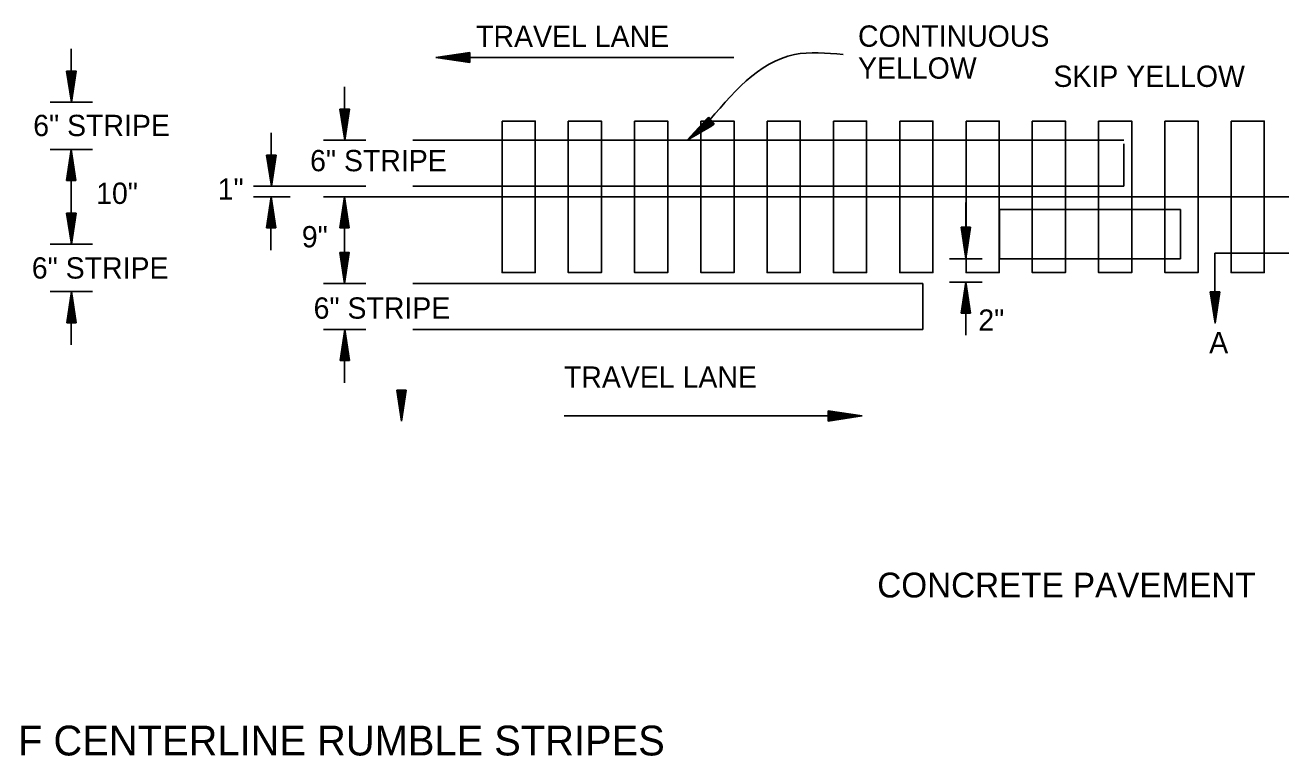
# Model space of a CAD drawing. Extents: x 28704 to 32542, y 50360 to 59122.
# Drawn here: x 31666 to 32184, y 50963 to 51264 of the extents above; entities that cross this region are included whole.
import ezdxf

# ---------------------------------------------------------------- set-up
doc = ezdxf.new("R2010")
doc.units = 0
doc.layers.add('Default', color=7, linetype='Continuous')
doc.layers.add('R_Alt Surface', color=7, linetype='Continuous')

msp = doc.modelspace()

# ---------------------------------------------------------------- linework, layer by layer
at = {"layer": 'Default'}
for p, q in [((31685.25, 51253.97), (31685.25, 51244.83)), ((31849.43, 51252.56), (31835.46, 51250.47)), ((31849.43, 51252.21), (31837.79, 51250.47)), ((31849.43, 51251.86), (31840.19, 51250.47)), ((31849.43, 51251.51), (31842.52, 51250.47)), ((31849.43, 51252.56), (31849.43, 51248.37)), ((31958.25, 51250.47), (31835.46, 51250.47)), ((31849.43, 51248.37), (31835.46, 51250.47)), ((31849.43, 51248.72), (31837.79, 51250.47)), ((31849.43, 51249.08), (31840.19, 51250.47)), ((31849.43, 51249.43), (31842.52, 51250.47)), ((31849.43, 51251.14), (31844.89, 51250.47)), ((31849.43, 51249.78), (31844.89, 51250.47)), ((31849.43, 51250.79), (31847.22, 51250.47)), ((31849.43, 51250.14), (31847.22, 51250.47)), ((31683.39, 51244.83), (31685.31, 51232.03)), ((31683.39, 51244.83), (31687.23, 51244.83)), ((31683.71, 51244.83), (31685.31, 51234.17)), ((31684.03, 51244.83), (31685.31, 51236.37)), ((31684.35, 51244.83), (31685.31, 51238.5)), ((31684.69, 51244.83), (31685.31, 51240.67)), ((31685.01, 51244.83), (31685.31, 51242.81)), ((31687.23, 51244.83), (31685.31, 51232.03)), ((31685.94, 51244.83), (31685.31, 51240.67)), ((31686.58, 51244.83), (31685.31, 51236.37)), ((31686.91, 51244.83), (31685.31, 51234.17)), ((31686.26, 51244.83), (31685.31, 51238.5)), ((31685.61, 51244.83), (31685.31, 51242.81)), ((31797.86, 51238.33), (31797.86, 51229.19)), ((31676.56, 51232.03), (31694.06, 51232.03)), ((31796, 51229.19), (31797.92, 51216.39)), ((31796, 51229.19), (31799.84, 51229.19)), ((31796.32, 51229.19), (31797.92, 51218.53)), ((31796.65, 51229.19), (31797.92, 51220.73)), ((31796.97, 51229.19), (31797.92, 51222.86)), ((31797.3, 51229.19), (31797.92, 51225.03)), ((31797.62, 51229.19), (31797.92, 51227.17)), ((31799.84, 51229.19), (31797.92, 51216.39)), ((31798.55, 51229.19), (31797.92, 51225.03)), ((31799.19, 51229.19), (31797.92, 51220.73)), ((31799.52, 51229.19), (31797.92, 51218.53)), ((31798.87, 51229.19), (31797.92, 51222.86)), ((31798.22, 51229.19), (31797.92, 51227.17)), ((31947.74, 51225.9), (31938.96, 51216.39)), ((31947.94, 51225.66), (31940.62, 51217.73)), ((31948.14, 51225.4), (31942.34, 51219.11)), ((31947.74, 51225.9), (31950.14, 51222.91)), ((31950.14, 51222.91), (31938.96, 51216.39)), ((31949.94, 51223.16), (31940.62, 51217.73)), ((31949.74, 51223.41), (31942.34, 51219.11)), ((31948.34, 51225.15), (31944, 51220.44)), ((31949.54, 51223.66), (31944, 51220.44)), ((31948.55, 51224.89), (31945.69, 51221.8)), ((31949.33, 51223.92), (31945.69, 51221.8)), ((31948.75, 51224.64), (31947.36, 51223.14)), ((31949.13, 51224.17), (31947.36, 51223.14)), ((31767.65, 51219.34), (31767.65, 51210.2)), ((31789.17, 51216.39), (31806.67, 51216.39)), ((31676.56, 51212.52), (31694.06, 51212.52)), ((31683.33, 51199.72), (31685.25, 51212.52)), ((31683.65, 51199.72), (31685.25, 51210.38)), ((31685.25, 51173.51), (31685.25, 51212.52)), ((31687.17, 51199.72), (31685.25, 51212.52)), ((31686.85, 51199.72), (31685.25, 51210.38)), ((31765.79, 51210.2), (31767.71, 51197.4)), ((31765.79, 51210.2), (31769.63, 51210.2)), ((31766.11, 51210.2), (31767.71, 51199.53)), ((31766.43, 51210.2), (31767.71, 51201.74)), ((31766.76, 51210.2), (31767.71, 51203.87)), ((31767.09, 51210.2), (31767.71, 51206.04)), ((31767.41, 51210.2), (31767.71, 51208.18)), ((31769.63, 51210.2), (31767.71, 51197.4)), ((31768.34, 51210.2), (31767.71, 51206.04)), ((31768.98, 51210.2), (31767.71, 51201.74)), ((31769.31, 51210.2), (31767.71, 51199.53)), ((31768.66, 51210.2), (31767.71, 51203.87)), ((31768.01, 51210.2), (31767.71, 51208.18)), ((31683.98, 51199.72), (31685.25, 51208.18)), ((31684.3, 51199.72), (31685.25, 51206.05)), ((31686.52, 51199.72), (31685.25, 51208.18)), ((31686.2, 51199.72), (31685.25, 51206.05)), ((31687.17, 51199.72), (31683.33, 51199.72)), ((31684.62, 51199.72), (31685.25, 51203.88)), ((31684.95, 51199.72), (31685.25, 51201.74)), ((31685.87, 51199.72), (31685.25, 51203.88)), ((31685.55, 51199.72), (31685.25, 51201.74)), ((31760.33, 51197.4), (31806.67, 51197.4)), ((31760.33, 51193.02), (31775.49, 51193.02)), ((31765.62, 51180.21), (31767.54, 51193.02)), ((31765.94, 51180.21), (31767.54, 51190.88)), ((31769.46, 51180.21), (31767.54, 51193.02)), ((31769.15, 51180.21), (31767.54, 51190.88)), ((31789.17, 51193.02), (32417.27, 51193.02)), ((31795.94, 51180.21), (31797.86, 51193.02)), ((31796.26, 51180.21), (31797.86, 51190.88)), ((31797.86, 51157.37), (31797.86, 51193.02)), ((31799.78, 51180.21), (31797.86, 51193.02)), ((31799.46, 51180.21), (31797.86, 51190.88)), ((32053.75, 51167.71), (32053.75, 51190.77)), ((31683.39, 51186.31), (31685.31, 51173.51)), ((31683.39, 51186.31), (31687.23, 51186.31)), ((31683.71, 51186.31), (31685.31, 51175.65)), ((31684.03, 51186.31), (31685.31, 51177.85)), ((31684.35, 51186.31), (31685.31, 51179.98)), ((31684.69, 51186.31), (31685.31, 51182.15)), ((31685.01, 51186.31), (31685.31, 51184.29)), ((31687.23, 51186.31), (31685.31, 51173.51)), ((31685.94, 51186.31), (31685.31, 51182.15)), ((31686.58, 51186.31), (31685.31, 51177.85)), ((31686.91, 51186.31), (31685.31, 51175.65)), ((31686.26, 51186.31), (31685.31, 51179.98)), ((31685.61, 51186.31), (31685.31, 51184.29)), ((31766.27, 51180.21), (31767.54, 51188.68)), ((31766.59, 51180.21), (31767.54, 51186.54)), ((31766.92, 51180.21), (31767.54, 51184.37)), ((31768.82, 51180.21), (31767.54, 51188.68)), ((31768.5, 51180.21), (31767.54, 51186.54)), ((31768.17, 51180.21), (31767.54, 51184.37)), ((31796.59, 51180.21), (31797.86, 51188.68)), ((31796.91, 51180.21), (31797.86, 51186.54)), ((31797.24, 51180.21), (31797.86, 51184.37)), ((31799.14, 51180.21), (31797.86, 51188.68)), ((31798.82, 51180.21), (31797.86, 51186.54)), ((31798.49, 51180.21), (31797.86, 51184.37)), ((31769.46, 51180.21), (31765.62, 51180.21)), ((31767.25, 51180.21), (31767.55, 51182.23)), ((31767.49, 51171.07), (31767.49, 51180.21)), ((31767.85, 51180.21), (31767.55, 51182.23)), ((31799.78, 51180.21), (31795.94, 51180.21)), ((31797.56, 51180.21), (31797.86, 51182.23)), ((31798.16, 51180.21), (31797.86, 51182.23)), ((32051.89, 51180.51), (32053.81, 51167.71)), ((32051.89, 51180.51), (32055.73, 51180.51)), ((32052.21, 51180.51), (32053.81, 51169.84)), ((32052.54, 51180.51), (32053.81, 51172.04)), ((32052.86, 51180.51), (32053.81, 51174.18)), ((32053.19, 51180.51), (32053.81, 51176.35)), ((32053.51, 51180.51), (32053.81, 51178.49)), ((32055.73, 51180.51), (32053.81, 51167.71)), ((32054.44, 51180.51), (32053.81, 51176.35)), ((32055.08, 51180.51), (32053.81, 51172.04)), ((32055.41, 51180.51), (32053.81, 51169.84)), ((32054.76, 51180.51), (32053.81, 51174.18)), ((32054.11, 51180.51), (32053.81, 51178.49)), ((31676.56, 51173.51), (31694.06, 51173.51)), ((31795.94, 51170.17), (31797.86, 51157.37)), ((31795.94, 51170.17), (31799.78, 51170.17)), ((31796.26, 51170.17), (31797.86, 51159.51)), ((31796.59, 51170.17), (31797.86, 51161.71)), ((31796.91, 51170.17), (31797.86, 51163.84)), ((31797.24, 51170.17), (31797.86, 51166.01)), ((31797.56, 51170.17), (31797.86, 51168.15)), ((31799.78, 51170.17), (31797.86, 51157.37)), ((31798.49, 51170.17), (31797.86, 51166.01)), ((31799.14, 51170.17), (31797.86, 51161.71)), ((31799.46, 51170.17), (31797.86, 51159.51)), ((31798.82, 51170.17), (31797.86, 51163.84)), ((31798.16, 51170.17), (31797.86, 51168.15)), ((32156.39, 51169.84), (32156.39, 51153.87)), ((32156.39, 51169.84), (32197.71, 51169.84)), ((31676.56, 51154), (31694.06, 51154)), ((31683.39, 51141.2), (31685.31, 51154)), ((31687.23, 51141.2), (31685.31, 51154)), ((31789.17, 51157.37), (31806.67, 51157.37)), ((32051.89, 51145.15), (32053.81, 51157.95)), ((32052.21, 51145.15), (32053.81, 51155.81)), ((32052.54, 51145.15), (32053.81, 51153.61)), ((32055.73, 51145.15), (32053.81, 51157.95)), ((32055.41, 51145.15), (32053.81, 51155.81)), ((32055.09, 51145.15), (32053.81, 51153.61)), ((32154.52, 51153.87), (32156.44, 51141.07)), ((32154.52, 51153.87), (32158.37, 51153.87)), ((32154.84, 51153.87), (32156.44, 51143.21)), ((32155.17, 51153.87), (32156.44, 51145.41)), ((32155.49, 51153.87), (32156.44, 51147.54)), ((32155.82, 51153.87), (32156.44, 51149.71)), ((32156.14, 51153.87), (32156.44, 51151.85)), ((32158.37, 51153.87), (32156.44, 51141.07)), ((32157.07, 51153.87), (32156.44, 51149.71)), ((32157.72, 51153.87), (32156.44, 51145.41)), ((32158.04, 51153.87), (32156.44, 51143.21)), ((32157.4, 51153.87), (32156.44, 51147.54)), ((32156.74, 51153.87), (32156.44, 51151.85)), ((31683.71, 51141.2), (31685.31, 51151.86)), ((31684.03, 51141.2), (31685.31, 51149.66)), ((31686.91, 51141.2), (31685.31, 51151.86)), ((31686.58, 51141.2), (31685.31, 51149.66)), ((32052.86, 51145.15), (32053.81, 51151.48)), ((32053.18, 51145.15), (32053.81, 51149.31)), ((32054.76, 51145.15), (32053.81, 51151.48)), ((32054.43, 51145.15), (32053.81, 51149.31)), ((31684.36, 51141.2), (31685.31, 51147.53)), ((31684.68, 51141.2), (31685.31, 51145.36)), ((31685.01, 51141.2), (31685.31, 51143.22)), ((31686.26, 51141.2), (31685.31, 51147.53)), ((31685.93, 51141.2), (31685.31, 51145.36)), ((31685.61, 51141.2), (31685.31, 51143.22)), ((32055.73, 51145.15), (32051.89, 51145.15)), ((32053.51, 51145.15), (32053.81, 51147.17)), ((32053.75, 51136.01), (32053.75, 51145.15)), ((32054.11, 51145.15), (32053.81, 51147.17)), ((31687.23, 51141.2), (31683.39, 51141.2)), ((31685.25, 51132.06), (31685.25, 51141.2)), ((31789.17, 51138.37), (31806.67, 51138.37)), ((31796, 51125.57), (31797.92, 51138.37)), ((31799.84, 51125.57), (31797.92, 51138.37)), ((31796.32, 51125.57), (31797.92, 51136.23)), ((31796.65, 51125.57), (31797.92, 51134.03)), ((31799.52, 51125.57), (31797.92, 51136.23)), ((31799.2, 51125.57), (31797.92, 51134.03)), ((31796.97, 51125.57), (31797.92, 51131.9)), ((31797.29, 51125.57), (31797.92, 51129.73)), ((31797.62, 51125.57), (31797.92, 51127.59)), ((31798.88, 51125.57), (31797.92, 51131.9)), ((31798.54, 51125.57), (31797.92, 51129.73)), ((31798.22, 51125.57), (31797.92, 51127.59)), ((31799.84, 51125.57), (31796, 51125.57)), ((31797.86, 51116.43), (31797.86, 51125.57)), ((31819.39, 51113.39), (31821.31, 51100.58)), ((31819.39, 51113.39), (31823.23, 51113.39)), ((31819.71, 51113.39), (31821.31, 51102.72)), ((31820.04, 51113.39), (31821.31, 51104.92)), ((31820.36, 51113.39), (31821.31, 51107.06)), ((31820.69, 51113.39), (31821.31, 51109.23)), ((31821.01, 51113.39), (31821.31, 51111.37)), ((31823.23, 51113.39), (31821.31, 51100.58)), ((31821.94, 51113.39), (31821.31, 51109.23)), ((31822.58, 51113.39), (31821.31, 51104.92)), ((31822.91, 51113.39), (31821.31, 51102.72)), ((31822.26, 51113.39), (31821.31, 51107.06)), ((31821.61, 51113.39), (31821.31, 51111.37)), ((31888.29, 51102.79), (32011.09, 51102.79)), ((31997.12, 51104.88), (32011.09, 51102.79)), ((31997.12, 51104.88), (31997.12, 51100.69)), ((31997.12, 51104.54), (32008.76, 51102.79)), ((31997.12, 51104.18), (32006.36, 51102.79)), ((31997.12, 51103.83), (32004.03, 51102.79)), ((31997.12, 51103.47), (32001.66, 51102.79)), ((31997.12, 51103.12), (31999.33, 51102.79)), ((31997.12, 51100.69), (32011.09, 51102.79)), ((31997.12, 51102.1), (32001.66, 51102.79)), ((31997.12, 51101.4), (32006.36, 51102.79)), ((31997.12, 51101.04), (32008.76, 51102.79)), ((31997.12, 51101.75), (32004.03, 51102.79)), ((31997.12, 51102.46), (31999.33, 51102.79))]:
    msp.add_line(p, q, dxfattribs=at)
for points in [[(31862.7, 51224.21), (31862.7, 51161.82), (31876.36, 51161.82), (31876.36, 51224.21)], [(31890.01, 51224.21), (31890.01, 51161.82), (31903.66, 51161.82), (31903.66, 51224.21)], [(31917.32, 51224.21), (31917.32, 51161.82), (31930.97, 51161.82), (31930.97, 51224.21)], [(31944.62, 51224.21), (31944.62, 51161.82), (31958.28, 51161.82), (31958.28, 51224.21)], [(31971.93, 51224.21), (31971.93, 51161.82), (31985.59, 51161.82), (31985.59, 51224.21)], [(31999.24, 51224.21), (31999.24, 51161.82), (32012.89, 51161.82), (32012.89, 51224.21)], [(32026.55, 51224.21), (32026.55, 51161.82), (32040.2, 51161.82), (32040.2, 51224.21)], [(32053.85, 51224.21), (32053.85, 51161.82), (32067.51, 51161.82), (32067.51, 51224.21)], [(32081.16, 51224.21), (32081.16, 51161.82), (32094.81, 51161.82), (32094.81, 51224.21)], [(32108.47, 51224.21), (32108.47, 51161.82), (32122.12, 51161.82), (32122.12, 51224.21)], [(32135.78, 51224.21), (32135.78, 51161.82), (32149.43, 51161.82), (32149.43, 51224.21)], [(32163.08, 51224.21), (32163.08, 51161.82), (32176.74, 51161.82), (32176.74, 51224.21)]]:
    msp.add_lwpolyline(points, close=True, dxfattribs=at)
msp.add_spline([(32003.27, 51251.65), (31983.16, 51251.65), (31946.24, 51222.24)], degree=3, dxfattribs=at)
at = {"layer": 'R_Alt Surface'}
for p, q in [((31826.02, 51216.39), (32118.82, 51216.39)), ((32118.82, 51214.93), (32118.82, 51197.4)), ((31826.02, 51197.4), (32118.82, 51197.4)), ((32067.66, 51187.85), (32067.66, 51167.45)), ((32067.66, 51187.85), (32142.23, 51187.85)), ((32142.23, 51187.85), (32142.23, 51167.45)), ((32047.11, 51167.45), (32060.51, 51167.45)), ((32067.66, 51167.45), (32142.23, 51167.45)), ((31826.02, 51157.37), (32036.01, 51157.37)), ((32036.01, 51157.37), (32036.01, 51138.37)), ((32047.11, 51157.95), (32060.51, 51157.95)), ((31826.02, 51138.37), (32036.01, 51138.37))]:
    msp.add_line(p, q, dxfattribs=at)
for points in [[(31683.32, 51244.83), (31687.18, 51244.83), (31685.31, 51232.03)], [(31795.93, 51229.19), (31799.79, 51229.19), (31797.92, 51216.39)], [(31949.19, 51222.32), (31947, 51225.07), (31938.96, 51216.39)], [(31765.72, 51210.2), (31769.58, 51210.2), (31767.71, 51197.4)], [(31683.32, 51186.31), (31687.18, 51186.31), (31685.31, 51173.51)], [(32051.82, 51180.51), (32055.68, 51180.51), (32053.81, 51167.71)], [(31795.88, 51170.17), (31799.73, 51170.17), (31797.86, 51157.37)], [(32154.46, 51153.87), (32158.32, 51153.87), (32156.44, 51141.07)]]:
    msp.add_lwpolyline(points, close=True, dxfattribs=at)

# ---------------------------------------------------------------- texts
at = {"layer": 'Default'}
for s, height, p in [('TRAVEL LANE', 8.7711, (31852.03, 51254.73)), ('CONTINUOUS ', 8.7711, (32009.36, 51254.87)), ('YELLOW', 8.771, (32009.36, 51241.71)), ('SKIP YELLOW', 8.7711, (32089.86, 51238.32)), ('6" STRIPE', 8.771, (31669.58, 51218.06)), ('6" STRIPE', 8.771, (31783.64, 51203.58)), ('1"', 8.771, (31745.58, 51191.84)), ('10"', 8.771, (31695.5, 51190.13)), ('9"', 8.771, (31780.23, 51172.23)), ('6" STRIPE', 8.771, (31669, 51159.37)), ('6" STRIPE', 8.771, (31785.09, 51142.85)), ('2"', 8.771, (32058.92, 51137.88)), ('A', 8.77, (32154.04, 51128.64)), ('TRAVEL LANE', 8.7711, (31888.2, 51114.41)), ('CONCRETE PAVEMENT', 10.2329, (32017.3, 51028.02))]:
    msp.add_text(s, height=height, dxfattribs=at).set_placement(p)
at = {"layer": 'R_Alt Surface'}
msp.add_text('LOCATION PLAN OF CENTERLINE RUMBLE STRIPES', height=12.2795, dxfattribs=at).set_placement((31514.6, 50962.95))

doc.saveas('drawing.dxf')
